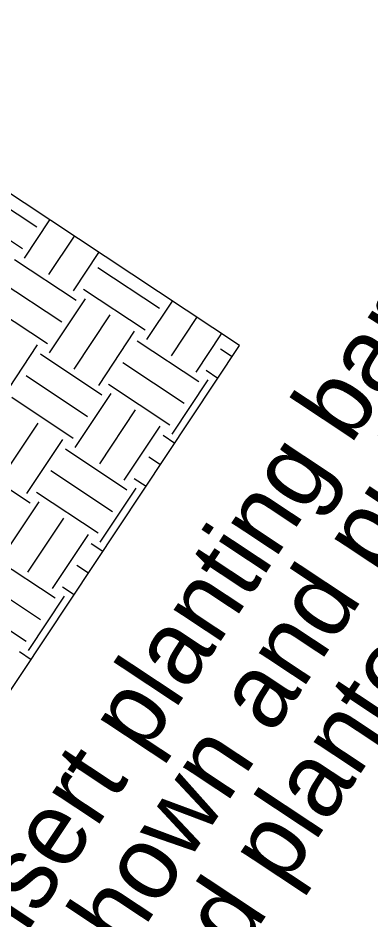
# Model space of a CAD drawing. Extents: x 561231 to 564935, y 589159 to 602519.
# Drawn here: x 564244.81 to 564264, y 589684.06 to 589733.17 of the extents above; entities that cross this region are included whole.
import ezdxf

# ---------------------------------------------------------------- set-up
doc = ezdxf.new("R2010")
doc.units = 0
doc.layers.add('Old_Level_1', color=7, linetype='Continuous')

msp = doc.modelspace()

# ---------------------------------------------------------------- linework, layer by layer
at = {"layer": 'Old_Level_1'}
for p, q in [((564256.856, 589715.337), (564229.97, 589733.175)), ((564242.491, 589724.017), (564245.837, 589721.797)), ((564241.71, 589722.839), (564245.055, 589720.619)), ((564245.156, 589720.097), (564246.539, 589722.182)), ((564246.495, 589719.209), (564247.877, 589721.294)), ((564247.833, 589718.321), (564249.215, 589720.406)), ((564244.627, 589720.024), (564247.972, 589717.805)), ((564249.158, 589719.594), (564252.504, 589717.374)), ((564243.845, 589718.846), (564247.191, 589716.626)), ((564248.377, 589718.415), (564251.722, 589716.196)), ((564243.064, 589717.668), (564246.409, 589715.448)), ((564246.525, 589714.947), (564248.478, 589717.893)), ((564251.824, 589715.673), (564253.206, 589717.758)), ((564247.863, 589714.059), (564249.816, 589717.005)), ((564253.162, 589714.785), (564254.544, 589716.871)), ((564249.201, 589713.171), (564251.155, 589716.117)), ((564254.5, 589713.898), (564255.882, 589715.983)), ((564251.294, 589715.601), (564254.639, 589713.381)), ((564233.634, 589680.321), (564256.856, 589715.337)), ((564243.926, 589712.43), (564245.879, 589715.375)), ((564255.826, 589715.17), (564256.464, 589714.746)), ((564246.033, 589714.881), (564249.378, 589712.661)), ((564250.512, 589714.422), (564253.857, 589712.203)), ((564255.044, 589713.992), (564255.683, 589713.569)), ((564245.252, 589713.702), (564248.597, 589711.483)), ((564249.731, 589713.244), (564253.076, 589711.025)), ((564253.192, 589710.524), (564255.145, 589713.469)), ((564244.47, 589712.524), (564247.815, 589710.305)), ((564247.917, 589709.782), (564249.87, 589712.727)), ((564249.255, 589708.894), (564251.208, 589711.84)), ((564243.956, 589708.168), (564245.91, 589711.114)), ((564250.593, 589708.006), (564252.546, 589710.952)), ((564245.294, 589707.281), (564247.248, 589710.226)), ((564252.7, 589710.457), (564253.339, 589710.034)), ((564247.387, 589709.71), (564250.732, 589707.49)), ((564251.919, 589709.279), (564252.558, 589708.856)), ((564242.126, 589708.99), (564245.471, 589706.77)), ((564246.606, 589708.531), (564249.951, 589706.312)), ((564251.137, 589708.101), (564251.776, 589707.677)), ((564245.824, 589707.353), (564249.169, 589705.134)), ((564249.285, 589704.632), (564251.239, 589707.578)), ((564244.01, 589703.891), (564245.963, 589706.836)), ((564245.348, 589703.003), (564247.301, 589705.948)), ((564246.686, 589702.115), (564248.64, 589705.061)), ((564248.793, 589704.566), (564249.432, 589704.143)), ((564243.48, 589703.818), (564246.825, 589701.599)), ((564248.012, 589703.388), (564248.651, 589702.964)), ((564242.699, 589702.64), (564246.044, 589700.421)), ((564247.23, 589702.21), (564247.869, 589701.786)), ((564241.917, 589701.462), (564245.262, 589699.243)), ((564245.378, 589698.741), (564247.332, 589701.687)), ((564244.886, 589698.675), (564245.525, 589698.251))]:
    msp.add_line(p, q, dxfattribs=at)

# ---------------------------------------------------------------- texts
for s, p in [(' as shown and pull handle ', (564244.44, 589672.717)), ('1. Insert planting bar ', (564240.139, 589675.569)), (' toward planter.', (564248.742, 589669.864))]:
    msp.add_text(s, height=4.01452, rotation=56.4482, dxfattribs=at).set_placement(p)

doc.saveas('drawing.dxf')
